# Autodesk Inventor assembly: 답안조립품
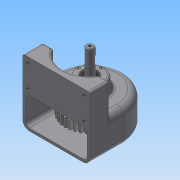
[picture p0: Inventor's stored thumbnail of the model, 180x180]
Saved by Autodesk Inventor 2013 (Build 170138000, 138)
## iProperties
Created: 2015-02
Part Number: 답안조립품
Document SubType Name: Assembly
Designer: Administrator
Author: Administrator
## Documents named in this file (10)
- C:\Documents and Settings\Administrator\바탕 화면\450214V1016\답안조립품.iam
- C:\Documents and Settings\Administrator\바탕 화면\450214V1016\1-본체.ipt
- C:\Documents and Settings\Administrator\바탕 화면\450214V1016\베어링 6001.ipt
- C:\Documents and Settings\Administrator\바탕 화면\450214V1016\축.ipt
- C:\Documents and Settings\Administrator\바탕 화면\450214V1016\키5x5.ipt
- C:\Documents and Settings\Administrator\바탕 화면\450214V1016\스퍼기어.ipt
- C:\Documents and Settings\Administrator\바탕 화면\450214V1016\축커버.ipt
- C:\Documents and Settings\Administrator\바탕 화면\450214V1016\오일실.ipt
- C:\Documents and Settings\Administrator\바탕 화면\450214V1016\M3x0.5.ipt
- C:\Documents and Settings\Administrator\바탕 화면\450214V1016\키4x4.ipt
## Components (5 placed, 2 different names)
1. 1-본체:1
2. M3x0.5:1
3. M3x0.5:2
4. M3x0.5:3
5. M3x0.5:4
